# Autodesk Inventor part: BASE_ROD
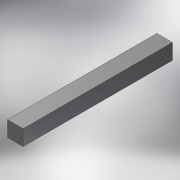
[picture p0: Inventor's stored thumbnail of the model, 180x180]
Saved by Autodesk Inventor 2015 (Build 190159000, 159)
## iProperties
Created: 2014-08
Part Number: BASE_ROD
Material: Steel, Mild
Document SubType Name: Modeling
Designer: lakshayg
Density: 7.85 g/cm^3
Appearance: Semi-Polished
Mass: 129.996 g
Surface Area: 58.08 cm^2
Volume: 16.56 cm^3
Author: lakshayg
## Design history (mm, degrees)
sketch "Sketch1"
  geometry: L1 (0, 0)-(-12, 0); L2 (-12, 0)-(-12, -12); L3 (-12, -12)-(0, -12); L4 (0, -12)-(0, 0)
  constraints: 8 end point, 2 parallel, 1 horizontal, 1 perpendicular
  dimensions: "d0" = 12 distance of L3.end L2.end; "d1" = 12 distance of L2.end L1.end
extrude "Extrusion1" new body sketch "Sketch1" distance "d2" = 115; taper "d3" = 0 deg
body "Solid1"
